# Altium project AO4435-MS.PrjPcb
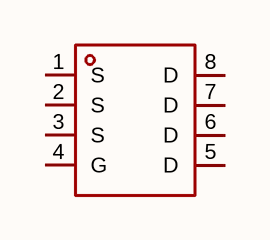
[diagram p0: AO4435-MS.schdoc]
1 sheet, 1 parts. Net scope: global (net labels, ports and power ports of the same name join across sheets).

## Sheet AO4435-MS.schdoc
size 127 x 101 mm

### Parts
Q?  ao4435-ms  [SOP-8_L5.0-W4.0-P1.27-LS6.0-BL]  (value not drawn)

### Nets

Not connected (* = marked no-connect by the designer): Q? 1(S) 2(S) 3(S) 4(G) 5(D) 6(D) 7(D) 8(D)

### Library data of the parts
Q? = ao4435-ms: 数量:1个P沟道;漏源电压(Vdss):30V;连续漏极电流(Id):9A;导通电阻(RDS(on)):20mΩ@10V;耗散功率(Pd):2.5W;阈值电压(Vgs(th)):3V@250uA;; Manufacturer: MSKSEMI(美森科); AddInBom: yes; ModelId: a3315c1c78f949e6bb82c6eaca1c53c7; ModelName: SOP-8_L5.0-W4.0-H1.8-LS6.2-P1.27; ModelTransform: 244.094,196.85,0,90,0,0,0,0,0; Number: 1个P沟道; Drain to Source Voltage: 30V; Current - Continuous Drain(Id): 9A; Pd - Power Dissipation: 2.5W; Gate Charge(Qg): 29nC; Input Capacitance(Ciss): 1.175nF; Reverse Transfer Capacitance (Crss@Vds): 190pF; Type: P沟道; Output Capacitance(Coss): 195pF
